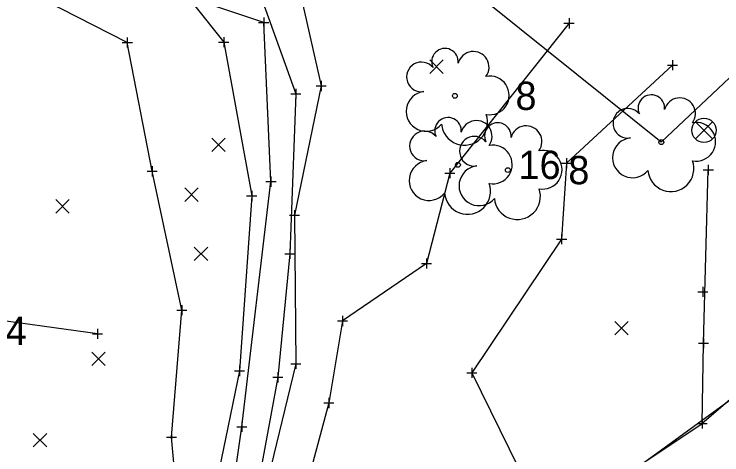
# Model space of a CAD drawing. Extents: x 2184635 to 2185378, y 369880 to 370486.
# Drawn here: x 2184837.8 to 2184907.9, y 370135.4 to 370179 of the extents above; entities that cross this region are included whole.
import ezdxf

# ---------------------------------------------------------------- set-up
doc = ezdxf.new("R2010")
doc.units = 0
for name, color, linetype in [('_CIVIL_CONSTRUCTION', 7, 'Continuous'), ('DR_X_Ditch', 7, 'Continuous'), ('GE_X_Alignment', 7, 'Continuous'), ('GE_X_Alignment_100_Cardinal_Points', 7, 'Continuous'), ('RD_X_Fence', 7, 'Continuous'), ('RW_X_CL', 7, 'Continuous'), ('SV_X_Break_Lines', 7, 'Continuous'), ('SV_X_Terrain_Boundary', 7, 'Continuous'), ('SV_X_Top_of_Bank', 7, 'Continuous'), ('VG_X_Text', 7, 'Continuous'), ('VG_X_Tree_Line_Lt', 7, 'Continuous')]:
    doc.layers.add(name, color=color, linetype=linetype)

msp = doc.modelspace()

# ---------------------------------------------------------------- linework, layer by layer
at = {"layer": '_CIVIL_CONSTRUCTION'}
for p, q in [((2184878.946, 370173.145), (2184880.279, 370174.48)), ((2184878.946, 370174.48), (2184880.279, 370173.145)), ((2184857.358, 370165.424), (2184858.692, 370166.759)), ((2184857.358, 370166.759), (2184858.692, 370165.424)), ((2184854.68, 370160.49), (2184856.013, 370161.825)), ((2184854.68, 370161.825), (2184856.013, 370160.49)), ((2184841.902, 370159.321), (2184843.235, 370160.656)), ((2184841.902, 370160.656), (2184843.235, 370159.321)), ((2184855.621, 370154.621), (2184856.955, 370155.956)), ((2184855.621, 370155.956), (2184856.955, 370154.621)), ((2184897.266, 370147.271), (2184898.6, 370148.606)), ((2184897.266, 370148.606), (2184898.6, 370147.271)), ((2184845.471, 370144.228), (2184846.804, 370145.563)), ((2184845.471, 370145.563), (2184846.804, 370144.228)), ((2184839.68, 370136.185), (2184841.013, 370137.52)), ((2184839.68, 370137.52), (2184841.013, 370136.185))]:
    msp.add_line(p, q, dxfattribs=at)
at = {"layer": 'DR_X_Ditch'}
msp.add_lwpolyline([(2184772.746, 370158.792), (2184783.456, 370154.562), (2184788.197, 370148.62), (2184793.425, 370146.92), (2184796.855, 370138.137), (2184799.486, 370133.714), (2184806.332, 370123.218), (2184820.592, 370119.162), (2184836.73, 370120.979), (2184847.133, 370119.834), (2184851.315, 370116.623), (2184858.24, 370123.687), (2184860.323, 370138.18), (2184863.22, 370162.438), (2184862.5, 370178.198), (2184848.599, 370182.845), (2184832.556, 370191.984), (2184837.703, 370200.441), (2184846.188, 370203.361)], dxfattribs=at)
at = {"layer": 'GE_X_Alignment'}
for centre in [(2184881.437, 370170.938), (2184901.88, 370166.351), (2184881.737, 370164.102), (2184886.673, 370163.583)]:
    msp.add_circle(centre, 0.24, dxfattribs=at)
for centre, radius, start, end in [((2184880.453, 370174.306), 1.317, 354.0047, 205.97412), ((2184883.263, 370173.767), 1.553, 323.82996, 165.0376), ((2184878.128, 370172.802), 1.471, 39.06254, 279.54124), ((2184884.897, 370170.974), 1.915, 259.14531, 101.45961), ((2184878.584, 370169.39), 1.974, 96.17219, 320.57371), ((2184900.896, 370169.718), 1.317, 354.0047, 205.97412), ((2184903.706, 370169.18), 1.553, 323.82996, 165.0376), ((2184898.57, 370168.215), 1.471, 39.06254, 279.54124), ((2184880.753, 370167.47), 1.317, 354.0047, 205.97412), ((2184882.383, 370168.333), 2.284, 184.94757, 19.45715), ((2184883.563, 370166.932), 1.553, 323.82996, 165.0376), ((2184885.689, 370166.951), 1.317, 354.0047, 205.97412), ((2184888.499, 370166.412), 1.553, 323.82996, 165.0376), ((2184905.34, 370166.386), 1.915, 259.14531, 101.45961), ((2184878.427, 370165.967), 1.471, 39.06254, 279.54124), ((2184883.363, 370165.447), 1.471, 39.06254, 279.54124), ((2184899.026, 370164.802), 1.974, 96.17219, 320.57371), ((2184885.197, 370164.138), 1.915, 259.14531, 101.45961), ((2184890.133, 370163.619), 1.915, 259.14531, 101.45961), ((2184878.883, 370162.554), 1.974, 96.17219, 320.57371), ((2184902.826, 370163.745), 2.284, 184.94757, 19.45715), ((2184883.819, 370162.034), 1.974, 96.17219, 320.57371), ((2184882.683, 370161.497), 2.284, 184.94757, 19.45715), ((2184887.619, 370160.978), 2.284, 184.94757, 19.45715)]:
    msp.add_arc(centre, radius, start, end, dxfattribs=at)
at = {"layer": 'GE_X_Alignment_100_Cardinal_Points'}
for p, q in [((2184906.953, 370166.675), (2184905.256, 370168.372)), ((2184905.256, 370166.675), (2184906.953, 370168.372))]:
    msp.add_line(p, q, dxfattribs=at)
msp.add_circle((2184906.105, 370167.523), 1.2, dxfattribs=at)
at = {"layer": 'RD_X_Fence'}
for points in [[(2185015.199, 370283.15), (2185015.458, 370270.123), (2185015.389, 370244.361), (2185014.511, 370228.509), (2185000.874, 370217.983), (2184983.945, 370203.779), (2184965.468, 370188.326), (2184938.367, 370166.286), (2184905.933, 370138.502), (2184906.07, 370146.446), (2184906.533, 370163.609)], [(2184709.157, 369984.536), (2184726.864, 369998.781), (2184769.898, 370032.731), (2184797.39, 370054.67), (2184814.475, 370067.872), (2184833.193, 370083.116), (2184887.166, 370125.991), (2184905.933, 370138.502)]]:
    msp.add_lwpolyline(points, dxfattribs=at)
at = {"layer": 'RW_X_CL'}
for p, q in [((2184862.5, 370178.698), (2184862.5, 370177.698)), ((2184892.741, 370178.612), (2184892.741, 370177.612)), ((2184862, 370178.198), (2184863, 370178.198)), ((2184862.5, 370178.198), (2184862.5, 370178.198)), ((2184892.241, 370178.112), (2184893.241, 370178.112)), ((2184892.741, 370178.112), (2184892.741, 370178.112)), ((2184848.491, 370176.215), (2184849.491, 370176.215)), ((2184848.991, 370176.715), (2184848.991, 370175.715)), ((2184848.991, 370176.215), (2184848.991, 370176.215)), ((2184858.038, 370176.245), (2184859.038, 370176.245)), ((2184858.538, 370176.745), (2184858.538, 370175.745)), ((2184858.538, 370176.245), (2184858.538, 370176.245)), ((2184902.988, 370174.472), (2184902.988, 370173.472)), ((2184902.488, 370173.972), (2184903.488, 370173.972)), ((2184902.988, 370173.972), (2184902.988, 370173.972)), ((2184868.19, 370172.411), (2184868.19, 370171.411)), ((2184865.693, 370171.626), (2184865.693, 370170.626)), ((2184867.69, 370171.911), (2184868.69, 370171.911)), ((2184868.19, 370171.911), (2184868.19, 370171.911)), ((2184865.193, 370171.126), (2184866.193, 370171.126)), ((2184865.693, 370171.126), (2184865.693, 370171.126)), ((2184892.504, 370164.77), (2184892.504, 370163.77)), ((2184851.447, 370163.965), (2184851.447, 370162.965)), ((2184880.94, 370163.787), (2184880.94, 370162.787)), ((2184892.004, 370164.27), (2184893.004, 370164.27)), ((2184892.504, 370164.27), (2184892.504, 370164.27)), ((2184906.033, 370163.609), (2184907.033, 370163.609)), ((2184906.533, 370164.109), (2184906.533, 370163.109)), ((2184906.533, 370163.609), (2184906.533, 370163.609)), ((2184850.947, 370163.465), (2184851.947, 370163.465)), ((2184851.447, 370163.465), (2184851.447, 370163.465)), ((2184863.22, 370162.938), (2184863.22, 370161.938)), ((2184880.44, 370163.287), (2184881.44, 370163.287)), ((2184880.94, 370163.287), (2184880.94, 370163.287)), ((2184862.72, 370162.438), (2184863.72, 370162.438)), ((2184863.22, 370162.438), (2184863.22, 370162.438)), ((2184861.311, 370161.54), (2184861.311, 370160.54)), ((2184860.811, 370161.04), (2184861.811, 370161.04)), ((2184861.311, 370161.04), (2184861.311, 370161.04)), ((2184865.546, 370159.618), (2184865.546, 370158.618)), ((2184865.046, 370159.118), (2184866.046, 370159.118)), ((2184865.546, 370159.118), (2184865.546, 370159.118)), ((2184891.51, 370156.749), (2184892.51, 370156.749)), ((2184892.01, 370157.249), (2184892.01, 370156.249)), ((2184892.01, 370156.749), (2184892.01, 370156.749)), ((2184864.601, 370155.292), (2184865.601, 370155.292)), ((2184865.101, 370155.792), (2184865.101, 370154.792)), ((2184865.101, 370155.292), (2184865.101, 370155.292)), ((2184878.623, 370154.831), (2184878.623, 370153.831)), ((2184878.123, 370154.331), (2184879.123, 370154.331)), ((2184878.623, 370154.331), (2184878.623, 370154.331)), ((2184905.99, 370152.042), (2184905.99, 370151.042)), ((2184905.49, 370151.542), (2184906.49, 370151.542)), ((2184905.99, 370151.542), (2184905.99, 370151.542)), ((2184853.898, 370149.727), (2184854.898, 370149.727)), ((2184854.398, 370150.227), (2184854.398, 370149.227)), ((2184854.398, 370149.727), (2184854.398, 370149.727)), ((2184870.304, 370149.148), (2184870.304, 370148.148)), ((2184869.804, 370148.648), (2184870.804, 370148.648)), ((2184870.304, 370148.648), (2184870.304, 370148.648)), ((2184846.036, 370147.883), (2184846.036, 370146.883)), ((2184845.536, 370147.383), (2184846.536, 370147.383)), ((2184846.036, 370147.383), (2184846.036, 370147.383)), ((2184906.07, 370146.946), (2184906.07, 370145.946)), ((2184905.57, 370146.446), (2184906.57, 370146.446)), ((2184906.07, 370146.446), (2184906.07, 370146.446)), ((2184865.671, 370144.911), (2184865.671, 370143.911)), ((2184860.114, 370144.198), (2184860.114, 370143.198)), ((2184865.171, 370144.411), (2184866.171, 370144.411)), ((2184865.671, 370144.411), (2184865.671, 370144.411)), ((2184883.111, 370144.026), (2184883.111, 370143.026)), ((2184859.614, 370143.698), (2184860.614, 370143.698)), ((2184860.114, 370143.698), (2184860.114, 370143.698)), ((2184863.901, 370143.574), (2184863.901, 370142.574)), ((2184882.611, 370143.526), (2184883.611, 370143.526)), ((2184883.111, 370143.526), (2184883.111, 370143.526)), ((2184863.401, 370143.074), (2184864.401, 370143.074)), ((2184863.901, 370143.074), (2184863.901, 370143.074)), ((2184868.443, 370140.53), (2184869.443, 370140.53)), ((2184868.943, 370141.03), (2184868.943, 370140.03)), ((2184868.943, 370140.53), (2184868.943, 370140.53)), ((2184860.323, 370138.68), (2184860.323, 370137.68)), ((2184905.433, 370138.502), (2184906.433, 370138.502)), ((2184905.933, 370139.002), (2184905.933, 370138.002)), ((2184905.933, 370138.502), (2184905.933, 370138.502)), ((2184853.364, 370137.647), (2184853.364, 370136.647)), ((2184859.823, 370138.18), (2184860.823, 370138.18)), ((2184860.323, 370138.18), (2184860.323, 370138.18)), ((2184852.864, 370137.147), (2184853.864, 370137.147)), ((2184853.364, 370137.147), (2184853.364, 370137.147))]:
    msp.add_line(p, q, dxfattribs=at)
at = {"layer": 'SV_X_Break_Lines'}
for points in [[(2184847.446, 370201.078), (2184834.811, 370193.51), (2184845.709, 370185.722), (2184859.639, 370184.834), (2184862.388, 370180.309), (2184865.693, 370171.126), (2184865.101, 370155.292), (2184863.901, 370143.074), (2184860.23, 370123.219), (2184851.862, 370116.242), (2184844.781, 370117.425), (2184833.754, 370119.669), (2184824.168, 370118.001), (2184814.096, 370116.756), (2184804.566, 370122.841), (2184797.93, 370133.989), (2184788.336, 370145.101), (2184776.293, 370154.453)], [(2184828.544, 370123.552), (2184841.621, 370126.777), (2184849.477, 370126.4), (2184851.069, 370127.042), (2184853.998, 370130.225), (2184853.364, 370137.147), (2184854.398, 370149.727), (2184851.447, 370163.465), (2184848.991, 370176.215), (2184835.789, 370182.952)], [(2184855.682, 370179.835), (2184858.538, 370176.245), (2184861.311, 370161.04), (2184860.114, 370143.698), (2184856.041, 370124.009), (2184852.867, 370119.623), (2184849.85, 370124.016), (2184847.684, 370125.007), (2184832.207, 370122.487)], [(2184892.741, 370178.112), (2184880.94, 370163.287), (2184878.623, 370154.331), (2184870.304, 370148.648), (2184868.943, 370140.53), (2184865.827, 370128.873), (2184863.667, 370123.888)], [(2184902.988, 370173.972), (2184892.504, 370164.27), (2184892.01, 370156.749), (2184883.111, 370143.526), (2184887.73, 370134.113), (2184887.918, 370129.231), (2184883.86, 370125.405), (2184879.575, 370122.684)], [(2184846.036, 370147.383), (2184834.103, 370149.02), (2184810.81, 370150.977), (2184801.527, 370152.27), (2184790.555, 370157.966), (2184778.39, 370163.174)]]:
    msp.add_lwpolyline(points, dxfattribs=at)
at = {"layer": 'SV_X_Terrain_Boundary'}
msp.add_lwpolyline([(2185048.788, 370280.746), (2184981.838, 370244.628), (2184966.756, 370227.412), (2184901.88, 370166.351), (2184859.946, 370200.015), (2184846.285, 370205.144), (2184825.044, 370216.074), (2184786.251, 370161.278), (2184768.884, 370142.96), (2184755.889, 370127.052), (2184768.662, 370083.987), (2184723.55, 370028.868), (2184709.399, 370017.08), (2184650.834, 369961.553), (2184636.069, 369950.037)], dxfattribs=at)
at = {"layer": 'SV_X_Top_of_Bank'}
msp.add_lwpolyline([(2184848.333, 370199.868), (2184841.014, 370194.314), (2184843.015, 370190.526), (2184848.448, 370188.396), (2184860.708, 370186.136), (2184865.589, 370183.475), (2184868.19, 370171.911), (2184865.546, 370159.118), (2184865.671, 370144.411), (2184861.572, 370127.549)], dxfattribs=at)
at = {"layer": 'VG_X_Tree_Line_Lt'}
msp.add_lwpolyline([(2185010.677, 370261.152), (2185009.496, 370230.83), (2184994.447, 370214.873), (2184919.447, 370148.63), (2184883.31, 370122.364), (2184845.078, 370084.673), (2184789.476, 370110.598), (2184762.675, 370135.815)], dxfattribs=at)

# ---------------------------------------------------------------- texts
at = {"layer": 'VG_X_Text'}
for s, p in [('8', (2184887.437, 370169.538)), ('16', (2184887.737, 370162.703)), ('8', (2184892.673, 370162.183)), ('24', (2184834.864, 370146.273))]:
    msp.add_text(s, height=2.8, dxfattribs=at).set_placement(p)

doc.saveas('drawing.dxf')
